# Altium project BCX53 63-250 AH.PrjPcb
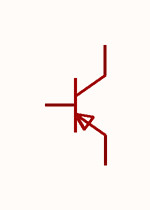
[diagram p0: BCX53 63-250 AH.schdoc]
1 sheet, 1 parts. Net scope: global (net labels, ports and power ports of the same name join across sheets).

## Sheet BCX53 63-250 AH.schdoc
size 127 x 101 mm

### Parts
Q?  bcx53(range:63-250)  [SOT-89-3_L4.5-W2.5-P1.50-LS4.2-BR]  (value not drawn)

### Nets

Not connected (* = marked no-connect by the designer): Q? 1(B) 2(C) 3(E)

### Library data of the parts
Q? = bcx53(range:63-250): 晶体管类型:PNP;集电极电流(Ic):1A;集射极击穿电压(Vceo):80V;耗散功率(Pd):500mW;直流电流增益(hFE):63;; Manufacturer: CJ(江苏长电/长晶); Symbol: BCX53 63-250 AH; AddInBom: yes; ModelId: 6db690b7897d4d18a30d90c1b89525ee; ModelName: SOT-89-3_L4.3-W2.5-H1.6-LS4.1-P1.50; ModelTransform: 161.417,169.291,0,180,0,0,-18.661,0,0; type: PNP; Current - Collector(Ic): 1A; Collector - Emitter Voltage VCEO: 80V; Pd - Power Dissipation: 500mW; DC Current Gain: 63; Transition frequency(fT): 50MHz; Current - Collector Cutoff: 100nA; Vce Saturation(VCE(sat)): 500mV; Emitter-Base Voltage(Vebo): 5V; Number: 1个PNP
